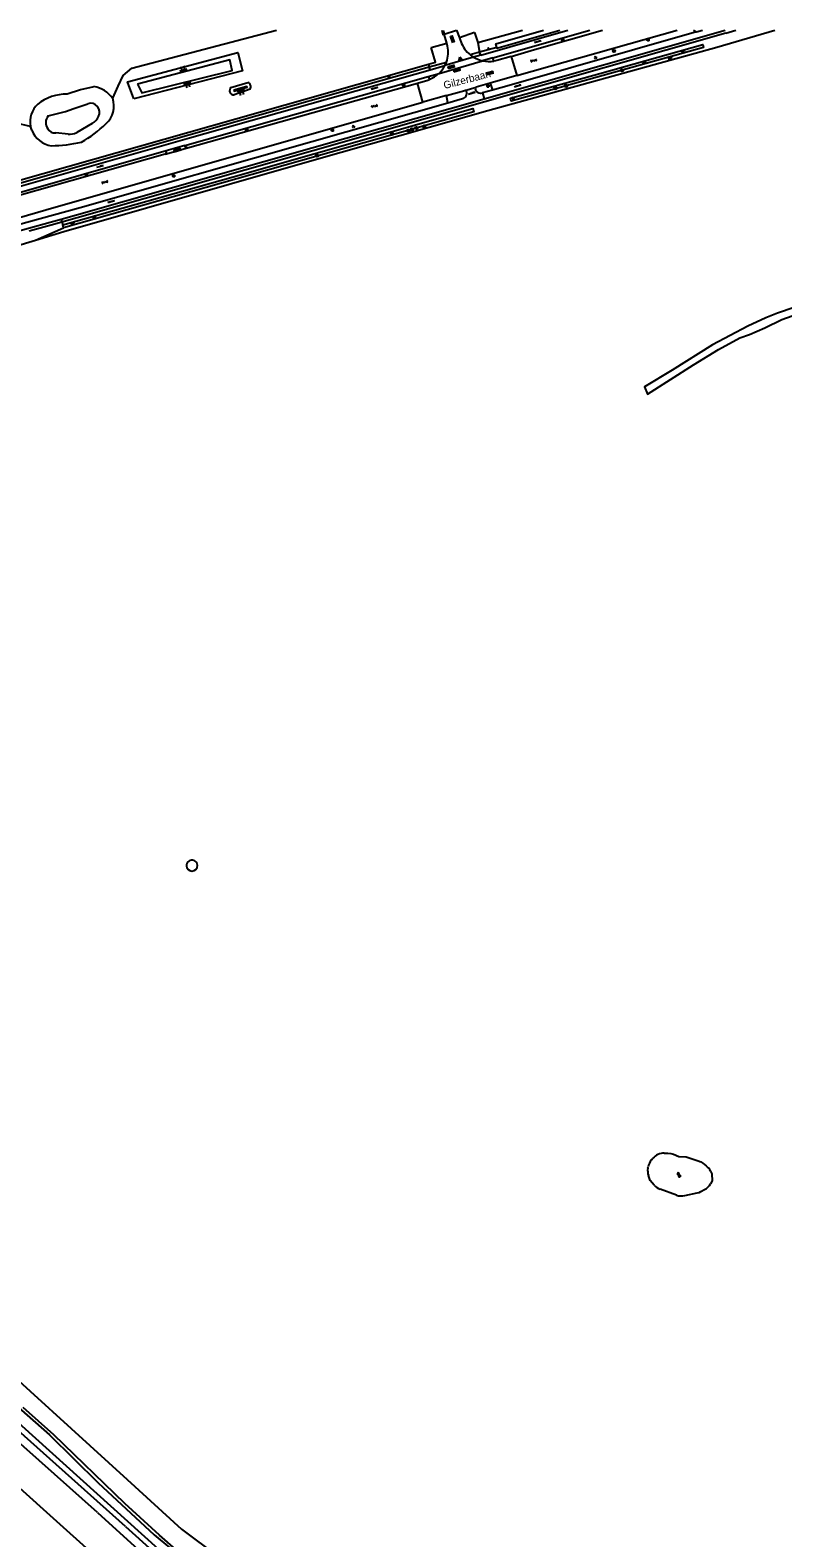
# Model space of a CAD drawing. Extents: x 126000 to 131009, y 393000 to 395500.
# Drawn here: x 126906 to 127157, y 394996 to 395500 of the extents above; entities that cross this region are included whole.
import ezdxf

# ---------------------------------------------------------------- set-up
doc = ezdxf.new("R2010")
doc.units = 0
for name, color, linetype in [('gg-afsc-erfafscheiding', 7, 'Continuous'), ('gg-afsc-faunaraster', 7, 'Continuous'), ('gg-anno-openbare ruimte label', 7, 'Continuous'), ('gg-bbg-gedigitaliseerde bijgebouw', 7, 'Continuous'), ('gg-knt-BGT kruinlijn', 7, 'Continuous'), ('gg-knt-bovenkant onderkant talud', 7, 'Continuous'), ('gg-knt-onverhard', 7, 'Continuous'), ('gg-knt-verharding', 7, 'Continuous'), ('gg-knt-verharding nz', 7, 'Continuous'), ('gg-kntw-bovenkant insteek waterloop', 7, 'Continuous'), ('gg-kntw-waterlijn', 7, 'Continuous'), ('gt-grn-groengrens', 7, 'Continuous'), ('gt-grn-groengrens NZ', 7, 'Continuous'), ('gt-grn-weggrens', 7, 'Continuous'), ('gt-symb-boom', 7, 'Continuous'), ('gt-symb-gesloten verharding', 7, 'Continuous'), ('gt-symb-groenvak', 7, 'Continuous'), ('gt-symb-klinker verharding', 7, 'Continuous'), ('gt-symb-lichtmast', 7, 'Continuous'), ('gt-symb-talud symbool', 7, 'Continuous'), ('gt-symb-tegel verharding', 7, 'Continuous'), ('gt-symb-waterafsluiter', 7, 'Continuous'), ('gt-symb-watersymbool', 7, 'Continuous'), ('gx-grn-maaiveld', 7, 'Continuous')]:
    doc.layers.add(name, color=color, linetype=linetype)

# ---------------------------------------------------------------- blocks, each defined once
blk = doc.blocks.new('gt0-TALUD_1')
at = {"layer": 'gt-symb-talud symbool'}
for p, q in [((-1, -1), (-1, 0)), ((-0.5, -2), (-0.5, 0)), ((0, -1), (0, 0)), ((0.5, -2), (0.5, 0)), ((1, -1), (1, 0))]:
    blk.add_line(p, q, dxfattribs=at)
blk = doc.blocks.new('gt0-KL1')
at = {"layer": 'gt-symb-klinker verharding'}
for p, q in [((-1.15, 0.3), (1.15, 0.3)), ((-1, -0.3), (-1, 0.3)), ((-0.5, 0.3), (-0.5, 0.45)), ((0, -0.3), (0, 0.3)), ((0.5, 0.3), (0.5, 0.45)), ((1, -0.3), (1, 0.3)), ((-1.15, -0.3), (1.15, -0.3)), ((-0.5, -0.45), (-0.5, -0.3)), ((0.5, -0.45), (0.5, -0.3))]:
    blk.add_line(p, q, dxfattribs=at)
blk = doc.blocks.new('gt0-WAFSL')
at = {"layer": 'gt-symb-waterafsluiter'}
for p, q in [((-0.5, -0.33), (0, 0.67)), ((0, 0.67), (0.5, -0.33)), ((0.5, -0.33), (-0.5, -0.33))]:
    blk.add_line(p, q, dxfattribs=at)
blk = doc.blocks.new('gt0-GRVAK')
at = {"layer": 'gt-symb-groenvak'}
for p, q in [((-0.11, 0.19), (-0.23, 0.24)), ((-0.18, 0.15), (0.09, 0.15)), ((-0.09, 0.21), (-0.16, 0.32)), ((-0.05, 0.21), (-0.05, 0.39)), ((0, 0.21), (0.06, 0.32)), ((0.01, 0.19), (0.13, 0.24)), ((0.26, -0.05), (0.2, 0.06)), ((0.3, -0.05), (0.3, 0.13)), ((0.35, -0.05), (0.41, 0.06)), ((-0.25, -0.23), (-0.36, -0.18)), ((-0.32, -0.26), (-0.05, -0.26)), ((-0.23, -0.21), (-0.29, -0.1)), ((-0.18, -0.2), (-0.18, -0.02)), ((-0.14, -0.21), (-0.07, -0.1)), ((-0.12, -0.23), (0, -0.18)), ((0.24, -0.07), (0.12, -0.02)), ((0.17, -0.11), (0.44, -0.11)), ((0.37, -0.07), (0.49, -0.02))]:
    blk.add_line(p, q, dxfattribs=at)
blk = doc.blocks.new('gt0-TEG1')
at = {"layer": 'gt-symb-tegel verharding'}
for p, q in [((-1.12, 0), (1.12, 0)), ((-0.9, -0.25), (-0.9, 0.25)), ((-0.45, -0.25), (-0.45, 0.25)), ((0, -0.25), (0, 0.25)), ((0.45, -0.25), (0.45, 0.25)), ((0.9, -0.25), (0.9, 0.25))]:
    blk.add_line(p, q, dxfattribs=at)
blk = doc.blocks.new('gt0-LMAST')
at = {"layer": 'gt-symb-lichtmast'}
for p, q in [((-0.18, 0.17), (-0.45, 0.44)), ((0, 0.25), (0, 0.62)), ((0.17, 0.17), (0.44, 0.44)), ((-0.25, 0), (-0.63, 0)), ((-0.18, -0.18), (-0.45, -0.45)), ((0, -0.25), (0, -0.63)), ((0.44, -0.45), (0.17, -0.18)), ((0.25, 0), (0.62, 0))]:
    blk.add_line(p, q, dxfattribs=at)
blk.add_circle((0, 0), 0.25, dxfattribs=at)
blk = doc.blocks.new('gt0-GESVH1')
at = {"layer": 'gt-symb-gesloten verharding'}
for p, q in [((-0.99, -0.26), (0.01, 0.24)), ((0.01, -0.26), (-0.99, 0.24)), ((0.01, 0.24), (1.01, -0.26)), ((1.01, 0.24), (0.01, -0.26))]:
    blk.add_line(p, q, dxfattribs=at)
blk = doc.blocks.new('gt0-BOOM')
at = {"layer": 'gt-symb-boom'}
for radius in [0.4, 0.2]:
    blk.add_circle((0, 0), radius, dxfattribs=at)
blk = doc.blocks.new('gt0-WA')
at = {"layer": 'gt-symb-watersymbool'}
for centre, start, end in [((-0.32, 0.02), 28.0725, 151.9275), ((0.43, 0.42), 208.0725, 331.9275), ((-0.32, -0.43), 28.0725, 151.9275), ((0.43, -0.03), 208.0725, 331.9275)]:
    blk.add_arc(centre, 0.425, start, end, dxfattribs=at)

msp = doc.modelspace()

# ---------------------------------------------------------------- linework, layer by layer
at = {"layer": 'gg-afsc-erfafscheiding'}
msp.add_line((126900.66, 395427.71), (126907.68, 395429.85), dxfattribs=at)
msp.add_lwpolyline([(126907.68, 395429.85), (126917.06, 395432.7), (127000, 395456.44), (127058.76, 395473.15), (127135.24, 395494.27), (127154.62, 395500)], dxfattribs=at)
at = {"layer": 'gg-afsc-faunaraster'}
for p, q in [((127054.33, 395499.25), (127055.42, 395495.84)), ((127055.42, 395495.84), (127070.28, 395500)), ((126888.17, 395445.82), (127038.91, 395488.6))]:
    msp.add_line(p, q, dxfattribs=at)
msp.add_lwpolyline([(127038.91, 395488.6), (127041.28, 395489.28), (127039.84, 395494.19)], dxfattribs=at)
at = {"layer": 'gg-bbg-gedigitaliseerde bijgebouw'}
for start, end in [(22.4575, 202.4984), (202.4864, 22.4695)]:
    msp.add_arc((126959.91, 395220.88), 1.83, start, end, dxfattribs=at)
at = {"layer": 'gg-knt-BGT kruinlijn'}
for points in [[(126897.38, 395043.79), (126912.33, 395030.66), (126928.57, 395014.65), (126947.25, 394997.3), (126958.42, 394988.04)], [(126955.42, 394991.58), (126949, 394997.13), (126937.44, 395007.73), (126913.76, 395030.71), (126903.52, 395039.81)]]:
    msp.add_lwpolyline(points, dxfattribs=at)
at = {"layer": 'gg-knt-bovenkant onderkant talud'}
for p, q in [((126972.92, 395480.81), (126978.58, 395482.52)), ((126979.35, 395480.29), (126973.97, 395478.39))]:
    msp.add_line(p, q, dxfattribs=at)
for points in [[(126940.44, 395477.09), (126938.4, 395482.68), (126975.21, 395492.49), (126976.78, 395486.44), (126940.44, 395477.09)], [(126941.72, 395482), (126943.18, 395479.04), (126973.35, 395486.49), (126972.55, 395490.09), (126941.72, 395482)], [(126973.9, 395479.93), (126973.98, 395479.65), (126978.35, 395480.9), (126978.26, 395481.17), (126973.9, 395479.93)], [(127413.72, 394641.72), (127411.81, 394641.27), (127401.51, 394644.62), (127375.04, 394659), (127324.74, 394688.25), (127293.65, 394707.21), (127252.58, 394735.71), (127214.39, 394764.25), (127171.95, 394796.59), (127140.11, 394823.15), (127103.96, 394853.54), (127049.18, 394901.47), (127015.66, 394931.28), (126969.21, 394973.96), (126887.15, 395047.96), (126780.06, 395142.95), (126762.04, 395161.58), (126750.89, 395173.5)], [(126762.96, 395173.44), (126773.5, 395166.13), (126785.57, 395153.73), (126802.36, 395138.31), (126837.04, 395108.39), (126862.36, 395083.12), (126886.98, 395062.3), (126938.24, 395015.69), (126956.41, 394999.19), (126968.75, 394989.9), (126990.86, 394970.88), (127017.54, 394945.12), (127036.8, 394927.65), (127078.32, 394890.88), (127143.1, 394834.92), (127163.57, 394815.37)]]:
    msp.add_lwpolyline(points, dxfattribs=at)
for centre, radius, start, end in [((126973.87, 395479.79), 1.39, 132.9042, 274.1276), ((126978.09, 395481.1), 1.5, 327.1534, 70.6828)]:
    msp.add_arc(centre, radius, start, end, dxfattribs=at)
at = {"layer": 'gg-knt-onverhard'}
msp.add_lwpolyline([(127161.08, 395407.37), (127155.55, 395405.43), (127151.63, 395403.87), (127145.62, 395401.09), (127133.8, 395394.91), (127120.37, 395386.44), (127111.08, 395380.84), (127112.05, 395378.41), (127127.42, 395388.19), (127135.84, 395393.3), (127142.95, 395397.2), (127146.16, 395398.27), (127151.29, 395400.56), (127156.99, 395403.29), (127162.32, 395405.18)], dxfattribs=at)
at = {"layer": 'gg-knt-verharding'}
for p, q in [((127044.17, 395498.64), (127044.18, 395498.65)), ((127045.02, 395495.7), (127044.17, 395498.64)), ((127044.18, 395498.65), (127048.28, 395500)), ((127048.3, 395500), (127049.25, 395497.4)), ((127056.41, 395491.69), (127085.44, 395500)), ((127057.51, 395477.06), (127137.99, 395500)), ((127060.37, 395490.75), (127092.78, 395500)), ((127068.41, 395484.8), (127122, 395500)), ((127128.42, 395499.41), (127130.49, 395500)), ((127045.32, 395494.69), (127045.02, 395495.7)), ((127049.25, 395497.4), (127049.6, 395496.42)), ((127049.6, 395496.42), (127049.68, 395496.23)), ((127039.51, 395486.77), (127044.39, 395488.15)), ((127056.41, 395491.69), (127053.97, 395490.99)), ((127060.37, 395490.75), (127056.97, 395489.78)), ((127066.6, 395491.23), (127068.41, 395484.8)), ((126957.54, 395461.48), (127038.83, 395484.54)), ((127038.83, 395484.54), (127042.44, 395485.57)), ((127068.41, 395484.8), (127059.57, 395482.29)), ((126958.43, 395460.7), (127035.21, 395482.32)), ((127037.08, 395475.89), (127035.21, 395482.32)), ((127044.99, 395478.14), (127037.08, 395475.89)), ((127044.99, 395478.14), (127051.04, 395479.88)), ((127051.04, 395479.88), (127054.88, 395480.96)), ((127059.57, 395482.29), (127054.88, 395480.96)), ((127060.26, 395479.97), (127056.95, 395479.03)), ((127045.43, 395475.74), (127050.33, 395477.14)), ((126951.32, 395459.7), (126889.53, 395442.06)), ((126951, 395458.6), (126958.43, 395460.7)), ((126957.54, 395461.48), (126951.32, 395459.7))]:
    msp.add_line(p, q, dxfattribs=at)
for points in [[(127043.33, 395500), (127043.77, 395498.53), (127044.17, 395498.64)], [(127043.82, 395500), (127043.98, 395499.47), (127044.18, 395498.65)], [(127128.42, 395499.41), (127065.86, 395481.55), (127060.26, 395479.97)], [(127066.6, 395491.23), (127074.32, 395493.51), (127097.08, 395500)], [(127044.39, 395488.15), (127044.67, 395488.73), (127044.91, 395489.34)], [(127052.9, 395491.72), (127053.42, 395491.34), (127053.97, 395490.99)], [(127066.6, 395491.23), (127061.77, 395489.89), (127061.29, 395489.77), (127060.81, 395489.68)], [(126888.83, 395443.98), (126959.12, 395464.01), (127039.51, 395486.77)], [(127035.21, 395482.32), (127038.66, 395483.32), (127039.21, 395483.52)], [(126867.72, 395425.54), (126904.75, 395435.86), (126922.55, 395440.73), (127000, 395462.81), (127045.43, 395475.74)], [(126868.13, 395427.51), (126914.57, 395441.01), (127037.08, 395475.89)], [(126916.2, 395436.85), (126921.27, 395438.26), (127000, 395460.67), (127057.51, 395477.06)], [(126951, 395458.6), (126895.39, 395442.91), (126889.84, 395441.25)], [(126951.32, 395459.7), (126951.3, 395459.06), (126951, 395458.6)], [(126958.43, 395460.7), (126957.79, 395460.93), (126957.54, 395461.48)], [(126865.53, 395422.83), (126905.24, 395433.85), (126912.56, 395435.84), (126916.2, 395436.85)]]:
    msp.add_lwpolyline(points, dxfattribs=at)
for centre, radius, start, end in [((127035.61, 395492.73), 9.9, 339.9261, 11.3796), ((127059.16, 395499.62), 10.07, 199.6831, 231.6111), ((127035.58, 395492.76), 9.94, 313.6259, 332.3292), ((127059.14, 395499.54), 9.99, 238.8358, 257.4891), ((127059.15, 395499.6), 10.06, 257.47, 279.4861), ((127035.63, 395492.72), 9.87, 291.2433, 313.5865), ((127049.91, 395478.94), 1.84, 282.9949, 20.1254), ((127051.15, 395479.36), 0.531, 23.0578, 102.8347), ((127055.02, 395480.48), 0.502, 107.0916, 192.6256), ((127056.34, 395480.78), 1.85, 192.6207, 289.1695)]:
    msp.add_arc(centre, radius, start, end, dxfattribs=at)
at = {"layer": 'gg-knt-verharding nz'}
for p, q in [((127042.44, 395485.57), (127056.97, 395489.78)), ((127053.97, 395490.99), (127044.39, 395488.15))]:
    msp.add_line(p, q, dxfattribs=at)
at = {"layer": 'gg-kntw-bovenkant insteek waterloop'}
for p, q in [((126937.69, 395000), (126747.76, 395170.02)), ((127113.44, 395122.54), (127113.9, 395123.07)), ((127112.23, 395119.75), (127112.3, 395120.17)), ((127121.81, 395110.75), (127116.35, 395112.71)), ((126937.69, 395000), (127000, 394944.01))]:
    msp.add_line(p, q, dxfattribs=at)
for points in [[(127061.71, 395494.25), (127061.42, 395495.41), (127077.39, 395500)], [(127061.71, 395494.25), (127061.79, 395493.95), (127082.85, 395500)], [(126927.15, 395481.11), (126922.62, 395480.05), (126918.21, 395478.61)], [(126906.39, 395466.56), (126906.17, 395467.2), (126906.01, 395467.85)], [(127117.68, 395124.8), (127118.9, 395124.8), (127119.86, 395124.71), (127120.79, 395124.43), (127122.56, 395123.71), (127125.02, 395123.5), (127129.06, 395122.19), (127129.86, 395121.86), (127130.58, 395121.39), (127131.74, 395120.49)], [(127114.3, 395114.1), (127112.96, 395115.61), (127112.4, 395117.28)], [(127133.14, 395118.78), (127133.6, 395117.88), (127133.73, 395115.54), (127133.14, 395114.52)], [(127124.59, 395110.58), (127128.68, 395111.49), (127129.33, 395111.68), (127129.95, 395111.96), (127131.16, 395112.61)], [(126928.32, 395004.74), (126985.13, 394953.04), (127004.36, 394935.98)]]:
    msp.add_lwpolyline(points, dxfattribs=at)
for centre, radius, start, end in [((126917.91, 395463.28), 15.33, 88.8869, 128.5716), ((126925.56, 395471.55), 9.7, 36.0045, 80.5548), ((126913.83, 395469.45), 7.99, 133.2713, 191.5408), ((126925.96, 395474.66), 7.89, 311.1243, 19.1526), ((126902.34, 395498.42), 41.37, 299.9092, 314.1282), ((126914.07, 395469.54), 8.24, 201.2151, 261.7991), ((126912.09, 395512.38), 51, 270.904, 282.319), ((127117.24, 395119.26), 5.02, 139.2268, 169.6089), ((127117.68, 395119.81), 5, 89.9866, 139.1749), ((127128.69, 395116.56), 4.98, 26.5056, 52.273), ((127117.13, 395118.86), 4.99, 169.6347, 198.4478), ((127118.04, 395117.41), 4.99, 221.6065, 250.2673), ((127123.5, 395115.44), 4.98, 250.1844, 282.596), ((127128.82, 395117.01), 4.99, 298.0359, 330.1117)]:
    msp.add_arc(centre, radius, start, end, dxfattribs=at)
at = {"layer": 'gg-kntw-waterlijn'}
for p, q in [((126926.59, 395468.78), (126921.41, 395465.75)), ((126918.5, 395465.27), (126914.39, 395465.68))]:
    msp.add_line(p, q, dxfattribs=at)
msp.add_lwpolyline([(126911.91, 395471.34), (126917.67, 395472.8), (126920.38, 395473.86), (126925.11, 395475.42)], dxfattribs=at)
for centre, radius, start, end in [((126926.02, 395472.54), 3.02, 333.3696, 107.5668), ((126914.38, 395469.12), 3.32, 138.0423, 218.0356), ((126923.68, 395473.5), 5.54, 301.6412, 335.3936), ((126914.06, 395468.24), 2.58, 206.7918, 277.129), ((126919.1, 395470.65), 5.41, 263.6058, 295.2358)]:
    msp.add_arc(centre, radius, start, end, dxfattribs=at)
at = {"layer": 'gt-grn-groengrens'}
for p, q in [((127054.33, 395499.25), (127049.25, 395497.4)), ((127127.51, 395500), (127128.42, 395499.41)), ((127039.84, 395494.19), (127045.02, 395495.7)), ((127038.91, 395488.6), (127039.2, 395487.72)), ((127056.41, 395491.69), (127055.98, 395492.61)), ((127060.81, 395489.68), (127060.37, 395490.75)), ((127038.83, 395484.54), (127039.21, 395483.52)), ((127039.51, 395486.77), (127039.2, 395487.72)), ((127045.43, 395475.74), (127044.99, 395478.14)), ((127059.57, 395482.29), (127060.26, 395479.97)), ((126906.01, 395467.85), (126901.15, 395468.89)), ((126907.68, 395429.85), (126917, 395434)), ((126916.2, 395436.85), (126916.47, 395435.89)), ((126916.47, 395435.89), (126916.73, 395434.96)), ((126917, 395434), (126916.73, 395434.96))]:
    msp.add_line(p, q, dxfattribs=at)
for points in [[(126933.41, 395477.25), (126935.3, 395481.28), (126936.93, 395484.9), (126939.82, 395487.26), (126988.1, 395500)], [(127130.81, 395494.22), (127066.55, 395476.22), (127066.33, 395477.22), (127096.22, 395485.55), (127130.58, 395495.21), (127130.81, 395494.22)], [(126916.73, 395434.96), (126973.63, 395451.01), (127053.77, 395473.87), (127054.06, 395472.71), (126917, 395434)]]:
    msp.add_lwpolyline(points, dxfattribs=at)
at = {"layer": 'gt-grn-groengrens NZ'}
for p, q in [((127138.24, 395499.04), (127057.78, 395476.1)), ((127138.24, 395499.04), (127141.62, 395500)), ((127055.42, 395495.84), (127055.98, 395492.61)), ((127061.71, 395494.25), (127055.98, 395492.61)), ((127039.2, 395487.72), (127044.91, 395489.34)), ((127055.98, 395492.61), (127052.9, 395491.72)), ((126958.85, 395464.97), (127039.2, 395487.72)), ((127057.78, 395476.1), (127000.27, 395459.7)), ((126888.49, 395444.92), (126958.85, 395464.97))]:
    msp.add_line(p, q, dxfattribs=at)
for points in [[(127000.27, 395459.7), (126921.54, 395437.3), (126916.47, 395435.89)], [(126916.47, 395435.89), (126912.82, 395434.88), (126905.51, 395432.88)]]:
    msp.add_lwpolyline(points, dxfattribs=at)
at = {"layer": 'gt-grn-weggrens'}
msp.add_line((127056.95, 395479.03), (127057.51, 395477.06), dxfattribs=at)
at = {"layer": 'gx-grn-maaiveld'}
msp.add_line((126928.32, 395004.74), (126835.96, 395087.02), dxfattribs=at)
msp.add_lwpolyline([(127010.21, 394915.85), (127005.81, 394919.84), (126987.8, 394936.06), (126970.22, 394951.91), (126952.38, 394967.85), (126934.43, 394984.02), (126916.93, 394999.74), (126899.1, 395015.84), (126881.52, 395031.64), (126863.57, 395047.81), (126845.87, 395063.72), (126828.28, 395079.53), (126810.56, 395095.46), (126794.23, 395110.16)], dxfattribs=at)

# ---------------------------------------------------------------- block references
at = {"layer": 'gt-symb-boom'}
for p in [(127100.89, 395493.01), (127123.91, 395492.92), (127111.04, 395489.11), (127119.67, 395490.62), (127103.53, 395486.58), (127081.29, 395480.61), (127084.9, 395481.4), (127037.53, 395467.81), (127026.72, 395465.33), (127032.25, 395466.44), (127033.41, 395466.88), (127034.9, 395467.29), (127001.66, 395458.06), (126927.33, 395437.54), (126920.07, 395435.45)]:
    msp.add_blockref('gt0-BOOM', p, dxfattribs=at)
at = {"layer": 'gt-symb-gesloten verharding'}
for p, rotation in [((127074.06, 395489.85), 15.843082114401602), ((127020.83, 395474.63), 15.843082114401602), ((126930.8, 395449.21), 15.787947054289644)]:
    msp.add_blockref('gt0-GESVH1', p, dxfattribs=dict(at, rotation=rotation))
at = {"layer": 'gt-symb-groenvak'}
for p in [(127059.01, 395493.75), (127094.74, 395490.88), (127025.69, 395484.52), (127067.21, 395477.36), (127013.88, 395467.81)]:
    msp.add_blockref('gt0-GRVAK', p, dxfattribs=at)
at = {"layer": 'gt-symb-klinker verharding'}
for p, rotation in [((127046.94, 395496.99), 109.99289398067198), ((127046.57, 395487.77), 16.205185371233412), ((127048.41, 395486.68), 16.205185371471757), ((127059.53, 395485.74), 15.064233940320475), ((126955.03, 395459.99), 15.55172489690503)]:
    msp.add_blockref('gt0-KL1', p, dxfattribs=dict(at, rotation=rotation))
at = {"layer": 'gt-symb-lichtmast'}
for p in [(127083.77, 395496.72), (127112.31, 395496.79), (127030.63, 395481.59), (127058.78, 395481.39), (126978.13, 395466.85), (127006.81, 395466.63), (126924.62, 395451.68), (126953.79, 395451.35)]:
    msp.add_blockref('gt0-LMAST', p, dxfattribs=at)
at = {"layer": 'gt-symb-talud symbool'}
for p, xscale, yscale, rotation in [((126957.13, 395486.05), 0.999802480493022, 0.9998024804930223, -165.2826888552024), ((126958.26, 395482.77), 1.0002204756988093, 1.0002204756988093, 13.88341803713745), ((126976.17, 395480.28), 0.9995729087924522, 0.9995729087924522, 15.969016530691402)]:
    msp.add_blockref('gt0-TALUD_1', p, dxfattribs=dict(at, xscale=xscale, yscale=yscale, rotation=rotation))
at = {"layer": 'gt-symb-tegel verharding'}
for p, rotation in [((127075.45, 395496.2), 15.843082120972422), ((127020.96, 395480.59), 15.843082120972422), ((127053.39, 395478.97), 16.26020470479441), ((127068.74, 395481.42), 15.843082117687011), ((126929.23, 395454.48), 15.787947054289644), ((126932.95, 395442.73), 15.787947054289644)]:
    msp.add_blockref('gt0-TEG1', p, dxfattribs=dict(at, rotation=rotation))
at = {"layer": 'gt-symb-waterafsluiter', "rotation": 18.000074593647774}
msp.add_blockref('gt0-WAFSL', (127049.59, 395490.4), dxfattribs=at)
at = {"layer": 'gt-symb-watersymbool', "rotation": -36.377067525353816}
msp.add_blockref('gt0-WA', (127122.54, 395117.52), dxfattribs=at)

# ---------------------------------------------------------------- texts
at = {"layer": 'gg-anno-openbare ruimte label'}
msp.add_text('Gilzerbaan', height=2.5, rotation=14.6, dxfattribs=at).set_placement((127044.29, 395480.32))

doc.saveas('drawing.dxf')
